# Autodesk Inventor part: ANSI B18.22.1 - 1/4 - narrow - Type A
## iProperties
Comments: To add or edit properties for Autodesk Inventor files, use iProperties.
Created: 2004-09
Part Number: ANSI B18.22.1 - 1/4 - narrow - Type A
Vendor: Autodesk Inc.
Document SubType Name: Modeling
Designer: John Blackburn
Material: Default
Description: Washer A
Standard: ANSI B18.22.1
Alert: To add or edit properties for Autodesk Inventor files, use iProperties.
Control State: 0
Master: False
Checked Out: False
Shininess: 64.0
Length Units: 11272
Angle Units: 11279
Time Units: 11290
Mass Units: 11286
Length Display Precision: 3
Angle Display Precision: 2
Compacted: True
Classification: un/spsc 31161807
Density: 0.0
Volumn: 0.0
Area: 0.0
PropertySet Name: Model Information
Author: John Blackburn
Revision Number: 8
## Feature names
1. Body [Extrusion]
